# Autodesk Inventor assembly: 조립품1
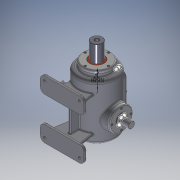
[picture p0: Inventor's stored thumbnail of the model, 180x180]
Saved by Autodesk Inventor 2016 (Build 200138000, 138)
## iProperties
Created: 2018-11
Part Number: 조립품1
Material: 일반
Document SubType Name: Assembly
Designer: user
Author: user
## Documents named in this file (15)
- C:\Users\user\Desktop\381121V1010\조립품1.iam
- C:\Users\user\Desktop\381121V1010\상부커버.ipt
- C:\Users\user\Desktop\381121V1010\슬라이드 커버.ipt
- C:\Users\user\Desktop\381121V1010\슬라이드.ipt
- C:\Users\user\Desktop\381121V1010\오일실.ipt
- 오일실.ipt
- C:\Users\user\Desktop\381121V1010\육각머리볼트 M4.ipt
- C:\Users\user\Desktop\381121V1010\축 커버.ipt
- C:\Users\user\Desktop\381121V1010\편심축.ipt
- C:\Users\user\Desktop\381121V1010\가변스프링.ipt
- C:\Users\user\Desktop\381121V1010\베어링 6205.ipt
- 베어링 6205.ipt
- C:\Users\user\Desktop\381121V1010\본체.ipt
- C:\Users\user\Desktop\381121V1010\볼트 M4x0.7.ipt
- C:\Users\user\Desktop\381121V1010\부시.ipt
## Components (13 placed, 2 different names)
1. 가변스프링:1
2. M4x0.7:1
3. M4x0.7:2
4. M4x0.7:3
5. M4x0.7:4
6. M4x0.7:5
7. M4x0.7:6
8. M4x0.7:7
9. M4x0.7:8
10. M4x0.7:9
11. M4x0.7:10
12. M4x0.7:11
13. M4x0.7:12
